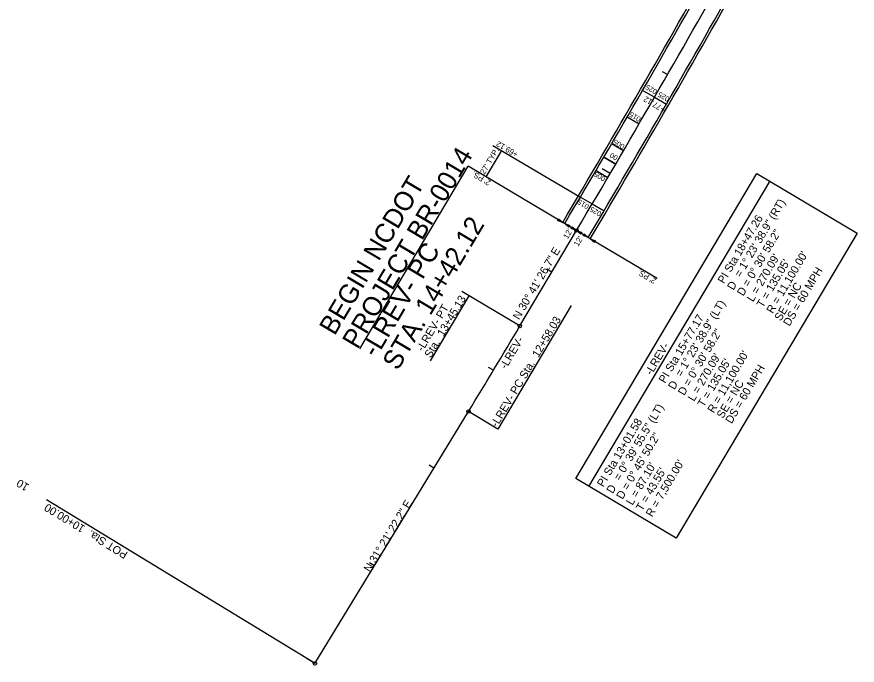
# Model space of a CAD drawing. Extents: x 2138032 to 2141863, y 405316 to 411953.
# Drawn here: x 2140198 to 2140932, y 409352 to 409919 of the extents above; entities that cross this region are included whole.
import ezdxf

# ---------------------------------------------------------------- set-up
doc = ezdxf.new("R2010")
doc.units = 0
for name, color, linetype in [('Prop Dimension', 7, 'Continuous'), ('Prop Dimension Text', 7, 'Continuous'), ('Prop EOT', 7, 'Continuous'), ('Prop Horizontal Alignment', 7, 'Continuous'), ('Prop Horizontal Alignment Curve and Spiral Data', 7, 'Continuous'), ('Prop Horizontal Alignment Direction Label', 7, 'Continuous'), ('Prop Horizontal Alignment Station Label', 7, 'Continuous'), ('Prop Horizontal Alignment Tick Label', 7, 'Continuous'), ('Prop Horizontal Alignment Tick Large', 7, 'Continuous'), ('Prop Horizontal Alignment Tick Small', 7, 'Continuous'), ('Prop Paved Shoulder', 7, 'Continuous'), ('Prop Superelevation  Arrow CELL', 7, 'Continuous'), ('Prop Superelevation Label', 7, 'Continuous'), ('Prop Terminator CELL', 7, 'Continuous')]:
    doc.layers.add(name, color=color, linetype=linetype)

msp = doc.modelspace()

# ---------------------------------------------------------------- linework, layer by layer
at = {"layer": 'Prop Dimension'}
for p, q in [((2140613.83, 409806.44), (2140690.33, 409761.28)), ((2140621.32, 409802.02), (2140607.66, 409778.99)), ((2140497.38, 409628.64), (2140592.1, 409788.23)), ((2140685.62, 409732.71), (2140592.1, 409788.23)), ((2140757.44, 409690.09), (2140698.95, 409724.8))]:
    msp.add_line(p, q, dxfattribs=at)
at = {"layer": 'Prop EOT'}
msp.add_line((2140698.95, 409724.8), (2140674.87, 409739.09), dxfattribs=at)
for radius in [11088, 11112]:
    msp.add_arc((2131141.64, 415397.43), radius, 329.309258, 330.70339, dxfattribs=at)
at = {"layer": 'Prop Horizontal Alignment'}
for p, q in [((2140637.41, 409648.54), (2140686.91, 409731.95)), ((2140458.25, 409353.56), (2140592.52, 409573.9))]:
    msp.add_line(p, q, dxfattribs=at)
for centre, radius, start, end in [((2131141.64, 415397.43), 11100, 329.309258, 330.70339), ((2134187.9, 413476.57), 7500, 328.643835, 329.309258)]:
    msp.add_arc(centre, radius, start, end, dxfattribs=at)
at = {"layer": 'Prop Horizontal Alignment Curve and Spiral Data'}
msp.add_line((2140697.83, 409508.34), (2140856.08, 409774.97), dxfattribs=at)
msp.add_lwpolyline([(2140686.25, 409515.21), (2140844.5, 409781.84), (2140932.36, 409729.69), (2140774.11, 409463.06)], close=True, dxfattribs=at)
at = {"layer": 'Prop Horizontal Alignment Station Label'}
for p, q in [((2140559.19, 409618), (2140592.97, 409674.92)), ((2140636.12, 409649.31), (2140586.61, 409678.7)), ((2140682.26, 409666.43), (2140618.09, 409558.32)), ((2140618.09, 409558.32), (2140592.52, 409573.9)), ((2140456.97, 409354.34), (2140223.42, 409496.66))]:
    msp.add_line(p, q, dxfattribs=at)
for centre in [(2140686.91, 409731.95), (2140637.41, 409648.54), (2140592.52, 409573.9), (2140458.25, 409353.56)]:
    msp.add_circle(centre, 1.5, dxfattribs=at)
at = {"layer": 'Prop Horizontal Alignment Tick Large'}
for p, q in [((2140716.33, 409781.8), (2140709.43, 409785.85)), ((2140458.25, 409353.56), (2140451.42, 409357.72))]:
    msp.add_line(p, q, dxfattribs=at)
at = {"layer": 'Prop Horizontal Alignment Tick Small'}
for p, q in [((2140766.53, 409868.28), (2140762.19, 409870.77)), ((2140665.42, 409695.73), (2140661.12, 409698.28)), ((2140614.26, 409609.8), (2140609.97, 409612.38)), ((2140562.32, 409524.35), (2140558.05, 409526.95)), ((2140510.29, 409438.95), (2140506.02, 409441.56))]:
    msp.add_line(p, q, dxfattribs=at)
at = {"layer": 'Prop Paved Shoulder'}
for radius in [11086, 11114]:
    msp.add_arc((2131141.64, 415397.43), radius, 329.309258, 330.70339, dxfattribs=at)
at = {"layer": 'Prop Superelevation  Arrow CELL'}
for p, q in [((2140755.11, 409848.46), (2140744.72, 409854.45)), ((2140755.11, 409848.46), (2140765.5, 409842.46)), ((2140741.58, 409825.09), (2140731.21, 409831.11)), ((2140728, 409801.75), (2140717.64, 409807.8)), ((2140710.83, 409796.16), (2140721.19, 409790.1)), ((2140721.19, 409790.1), (2140710.83, 409796.16)), ((2140704.01, 409784.53), (2140714.36, 409778.45)), ((2140690.33, 409761.28), (2140700.67, 409755.18)), ((2140700.67, 409755.18), (2140711, 409749.08))]:
    msp.add_line(p, q, dxfattribs=at)
at = {"layer": 'Prop Terminator CELL'}
for points in [[(2140671.16, 409742.26), (2140674.87, 409739.09), (2140670.28, 409740.83), (2140671.24, 409741.25)], [(2140680.31, 409734.91), (2140676.59, 409738.07), (2140681.19, 409736.34), (2140680.22, 409735.92)], [(2140683.2, 409735.12), (2140686.91, 409731.95), (2140682.32, 409733.68), (2140683.28, 409734.1)], [(2140690.63, 409728.78), (2140686.91, 409731.95), (2140691.51, 409730.21), (2140690.54, 409729.79)], [(2140693.52, 409728.99), (2140697.23, 409725.82), (2140692.64, 409727.56), (2140693.6, 409727.98)], [(2140702.67, 409721.64), (2140698.95, 409724.8), (2140703.55, 409723.07), (2140702.58, 409722.65)]]:
    msp.add_lwpolyline(points, close=True, dxfattribs=at)

# ---------------------------------------------------------------- texts
at = {"layer": 'Prop Dimension'}
for s, p in [('PROJECT BR-0014', (2140495.51, 409627.48)), ('BEGIN NCDOT ', (2140475.41, 409639.41)), ('STA. 14+42.12', (2140530.64, 409608.89)), ('-LREV- PC', (2140511.82, 409620.07))]:
    msp.add_text(s, height=16.7, rotation=59.30926, dxfattribs=at).set_placement(p)
at = {"layer": 'Prop Dimension Text'}
for s, rotation, p in [('+77.12', 149.30926, (2140765.19, 409839.12)), ('+69.12', 149.30926, (2140636.45, 409799.92)), ("27' TYP.", 59.30926, (2140606.55, 409780.56)), ("2' PS.", 149.30926, (2140612.48, 409775.2)), ("12'", 59.30926, (2140679.2, 409724.09)), ("12'", 59.30926, (2140688.45, 409717.69)), ("2' PS.", 149.30926, (2140757.12, 409689.35))]:
    msp.add_text(s, height=5, rotation=rotation, dxfattribs=at).set_placement(p)
at = {"layer": 'Prop Horizontal Alignment Curve and Spiral Data'}
for s, p in [('= 1%%d 23\' 38.9" (RT)', (2140830.43, 409690.51)), ('PI Sta 18+47.26', (2140815.87, 409684.99)), ('D = 0%%d 30\' 58.2"', (2140832.73, 409674.2)), ("L = 270.09'", (2140841.33, 409669.1)), ("R = 11,100.00'", (2140858.53, 409658.89)), ("T = 135.05'", (2140849.93, 409663.99)), ('DS = 60 MPH', (2140873.16, 409647.84)), ('D', (2140824.13, 409679.3)), ('SE = NC', (2140865.53, 409652.37)), ('= 1%%d 23\' 38.9" (LT)', (2140778.82, 409603.54)), ('PI Sta 15+77.17', (2140764.26, 409598.02)), ('D = 0%%d 30\' 58.2"', (2140781.11, 409587.24)), ('-LREV-', (2140752.48, 409605.02)), ("L = 270.09'", (2140789.71, 409582.13)), ("T = 135.05'", (2140798.31, 409577.03)), ("R = 11,100.00'", (2140806.91, 409571.92)), ('DS = 60 MPH', (2140822.58, 409562.62)), ('D', (2140772.51, 409592.34)), ('SE = NC', (2140814.95, 409567.15)), ('= 0%%d 39\' 55.5" (LT)', (2140724.92, 409512.74)), ('PI Sta 13+01.58', (2140710.36, 409507.22)), ('D = 0%%d 45\' 50.2"', (2140727.22, 409496.43)), ("R = 7,500.00'", (2140753.01, 409481.12)), ("L = 87.10'", (2140735.82, 409491.33)), ("T = 43.55'", (2140744.41, 409486.22)), ('D', (2140718.62, 409501.54))]:
    msp.add_text(s, height=7, rotation=59.30926, dxfattribs=at).set_placement(p)
at = {"layer": 'Prop Horizontal Alignment Direction Label'}
for s, rotation, p in [('N 30%%d 41\' 26.7" E', 59.30926, (2140636.75, 409653.46)), ('-LREV-', 59.30926, (2140625.36, 409610.34)), ('N 31%%d 21\' 22.2" E', 58.64384, (2140506.35, 409432.87))]:
    msp.add_text(s, height=7, rotation=rotation, dxfattribs=at).set_placement(p)
at = {"layer": 'Prop Horizontal Alignment Station Label'}
for s, rotation, p in [('Sta.  13+45.13', 59.30926, (2140559.43, 409619.98)), ('-LREV- PT ', 59.30926, (2140552.56, 409625.78)), ('-LREV- PC Sta.  12+58.03', 59.30926, (2140617.5, 409559.61)), ('POT Sta.  10+00.00', 148.64384, (2140295.22, 409450.56))]:
    msp.add_text(s, height=7, rotation=rotation, dxfattribs=at).set_placement(p)
at = {"layer": 'Prop Horizontal Alignment Tick Label'}
msp.add_text('10', height=7, rotation=148.64384, dxfattribs=at).set_placement((2140208.89, 409509.61))
at = {"layer": 'Prop Superelevation Label'}
for s, p in [('025', (2140757.95, 409854.59)), ('025', (2140768.75, 409848.17)), ('015', (2140743.74, 409830.64)), ('005', (2140729.52, 409806.69)), ('00', (2140723.66, 409796.81)), ('005', (2140712.81, 409778.53)), ('015', (2140698.39, 409754.23)), ('025', (2140709.21, 409747.85))]:
    msp.add_text(s, height=4.5, rotation=149.30926, dxfattribs=at).set_placement(p)

doc.saveas('drawing.dxf')
